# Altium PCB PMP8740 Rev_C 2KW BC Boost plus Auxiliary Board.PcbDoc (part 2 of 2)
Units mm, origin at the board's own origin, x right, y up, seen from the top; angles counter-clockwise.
Board outline 261.75 x 149.86 mm, 2 copper layers (Top Layer, Bottom Layer), stack 1.575 mm thick; 147 components, 79 nets, 365 pads, 168 vias.
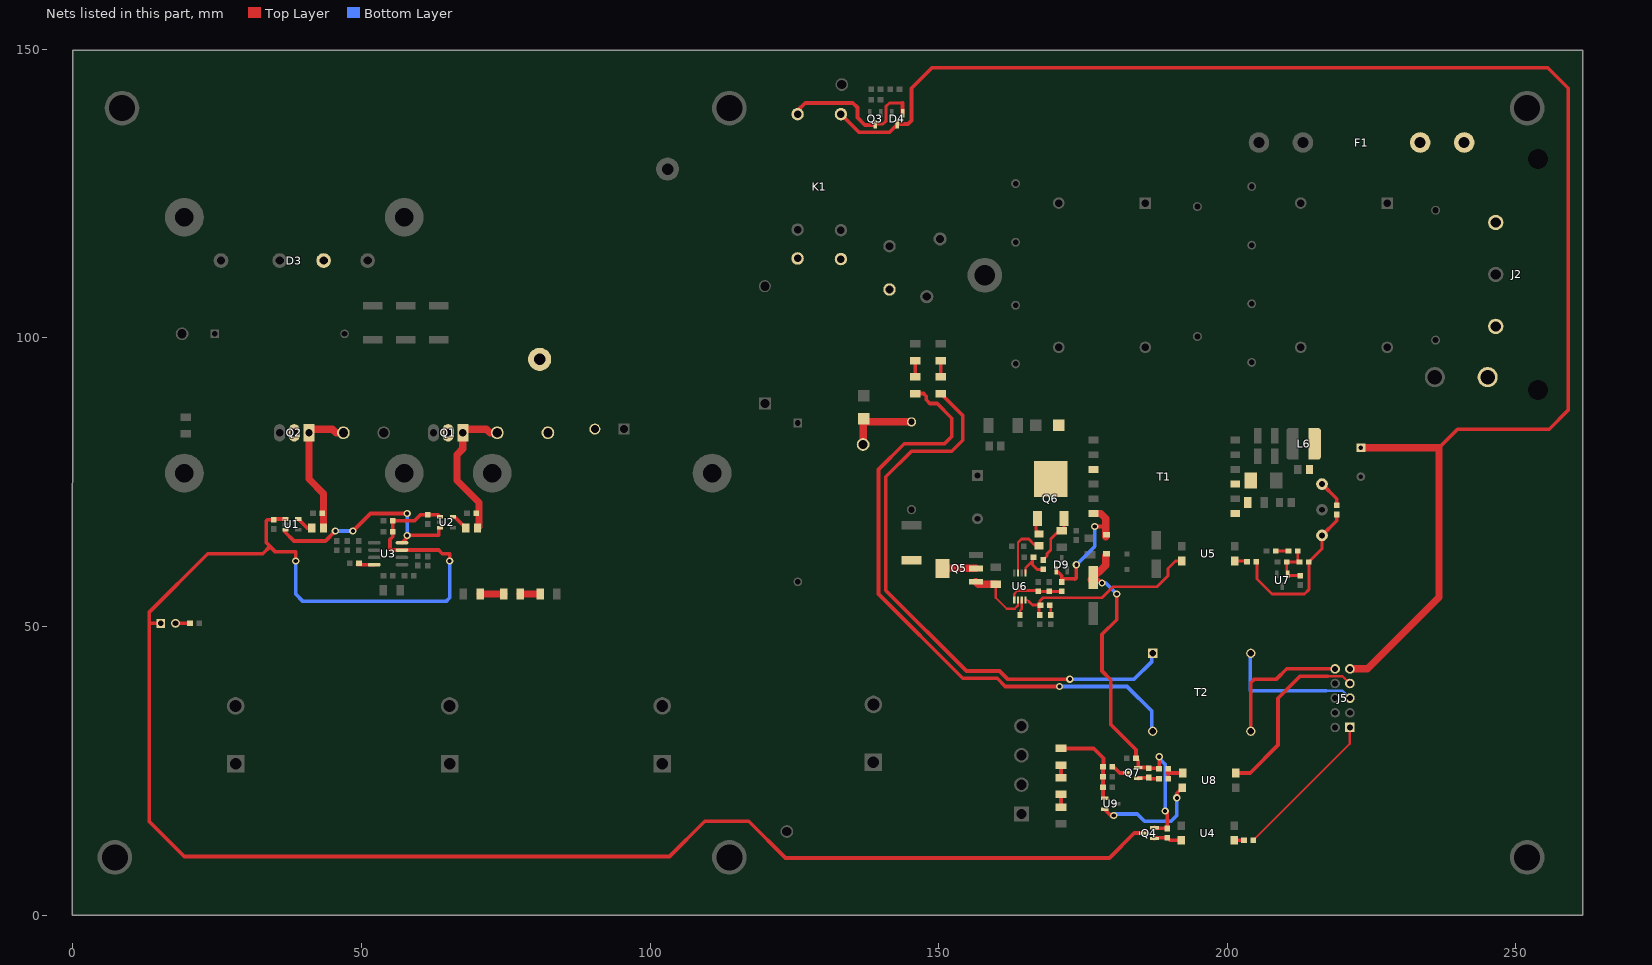
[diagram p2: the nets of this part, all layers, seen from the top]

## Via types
v1: diameter 1.27, hole 0.711, Top Layer to Bottom Layer, tented top, 131 vias
v2: diameter 1.27, hole 0.711, Top Layer to Bottom Layer, 35 vias
v3: diameter 0.889, hole 0.508, Top Layer to Bottom Layer, tented top, 2 vias

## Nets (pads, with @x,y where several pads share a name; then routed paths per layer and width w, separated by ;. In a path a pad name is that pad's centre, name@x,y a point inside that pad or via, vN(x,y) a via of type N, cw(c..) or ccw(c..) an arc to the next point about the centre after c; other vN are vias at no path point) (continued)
NetC34_2: C34.2 R29.1 R32.2 R35.1 U7.1 | length 8.3
  Top Layer w0.508: R29.1@212.214,61.485 R32.2@212.214,63.085 ; R29.1@212.519,61.18 C34.2@210.309,61.18 210.309,59.205 U7.1@210.459,59.055 210.709,58.805 R35.1@212.684,58.805
NetC35_2: C35.2 R32.1 | length 2.2
  Top Layer w0.508: C35.2@208.404,63.085 R32.1@210.614,63.085
NetC36_1: C36.1 R31.1 U6.5 | length 6.1
  Top Layer w0.381: U6.5@165.049,59.268 165.049,60.147 166.243,61.341
  Top Layer w0.508: C36.1@166.408,61.976 166.243,61.811 166.243,61.341 166.243,60.706 167.043,59.906 R31.1@168.148,59.906
NetC37_1: C37.1 U6.3 | length 2.8
  Top Layer w0.381: C37.1@164.089,51.981 164.089,52.731 164.398,53.041 U6.3@164.398,54.605
NetC38_1: C38.1 R33.2 U5.4 U6.4 | length 33.2
  Top Layer w0.305: U6.4@165.049,54.605 165.359,54.605 165.608,54.356
  Top Layer w0.508: 165.608,54.356 166.243,53.721 167.348,53.721 167.348,52.146 C38.1@167.513,51.981 ; R33.2@167.513,53.886 167.513,54.446 168.058,54.991 178.308,54.991 180.213,56.896 187.833,56.896 189.738,58.801 189.738,60.071 191.008,61.341 U5.4@192.11,61.341
NetC39_1: C39.1 R26.1 R27.2 U6.1 | length 9.6
  Top Layer w0.305: 163.068,55.626 163.098,55.596
  Top Layer w0.381: 163.068,55.626 163.703,56.261 ; U6.1@163.098,54.605 163.098,55.596
  Top Layer w0.508: 163.703,56.261 167.099,56.261 C39.1@167.264,56.096 R27.2@169.169,56.096 R26.1@171.323,56.096
NetC40_1: C40.1 R33.1 | length 1.9
  Top Layer w0.508: R33.1@168.948,53.721 169.418,53.251 C40.1@169.418,51.981
NetC42_1: C42.1 R40.1 R42.1 R43.2 U9.1 | length 15.2
  Top Layer w0.635: R40.1@171.196,28.882 176.858,28.882 178.562,27.178 178.562,25.841 R42.1@178.469,25.748 C42.1@178.469,23.97 178.469,20.509 U9.1@178.732,20.246
NetD2_2: D2.2 L1.2 Q1.2 Q2.2 TP2.1
NetD3_3: D3.3 K1.3 K1.4 RT1.2
NetD4_1: D4.1 K1.1 Q3.3 | length 26.8
  Top Layer w0.508: Q3.3@138.983,137.051 140.353,137.051 140.843,137.541 140.843,140.081 141.478,140.716 143.743,140.716
  Top Layer w0.635: K1.1@125.552,138.76 125.552,139.395 126.873,140.716 135.128,140.716 135.928,139.916 135.928,138.176 137.198,136.906 138.838,136.906 Q3.3@138.983,137.051 ; D4.1@143.743,138.951 143.743,140.716
NetD5_1: D5.1 RF1.2 TP15.1 | length 13
  Top Layer w1.27: TP15.1@136.906,81.534 136.906,85.884 D5.1@137.033,86.011 137.593,85.451 RF1.2@145.288,85.451
NetD6_2: D6.2 Q6.4 T1.9
NetD7_2: D7.2 R23.1 T1.1 T1.3
NetD8_2: D8.2 D9.1 R26.2 T1.12 | length 23
  Top Layer w0.635: D9.1@170.373,59.756 171.323,58.806 171.323,58.251 ; R26.2@171.323,57.696 171.323,58.251 ; v1(173.863,60.706) 173.863,58.448 173.601,58.186 173.536,58.251 171.323,58.251 ; v1(177.038,67.332) 178.667,67.332 178.943,67.056
  Top Layer w1.27: T1.12@176.838,69.596 178.068,69.596 178.943,68.721 178.943,67.056 D8.2@178.943,65.518
  Bottom Layer w0.635: v1(173.863,60.706) 177.038,63.881 v1(177.038,67.332)
NetF1_1: F1.1 F1.2 J2.2
NetJ2_1: J2.1 TP11.1
NetJ6_2: J6.2 R48.1 | length 2.5
  Top Layer w0.635: J6.2@17.78,50.546 R48.1@20.282,50.546
NetQ1_1: Q1.1 R2.2 R4.2 TP5.1 | length 28.1
  Top Layer w0.635: R4.2@69.888,69.596 70.104,69.38 R2.2@70.104,67.056
  Top Layer w1.27: R2.2@70.104,67.056 70.358,67.31 70.358,71.501 66.548,75.311 66.548,79.756 67.569,80.777 67.569,84.201 71.628,84.201 72.263,83.566 TP5.1@73.533,83.566
NetQ2_1: Q2.1 R1.2 R3.2 TP4.1 | length 24.4
  Top Layer w1.27: R1.2@43.434,67.056 43.434,73.025 40.899,75.56 40.899,84.201 44.958,84.201 45.593,83.566 TP4.1@46.863,83.566
NetQ4_1: Q4.1 R19.1 U4.4 | length 4.9
  Top Layer w0.635: Q4.1@187.391,13.274 187.541,13.424 R19.1@189.616,13.424 190.086,12.954 U4.4@191.988,12.954
NetQ5_1: Q5.1 R25.1 U6.2 | length 11.8
  Top Layer w0.381: R25.1@159.893,57.351 159.893,54.991 161.798,53.086 163.2,53.086 163.748,53.634 U6.2@163.748,54.605
  Top Layer w1.27: Q5.1@156.443,57.771 156.863,57.351 R25.1@159.893,57.351
NetQ5_2: Q5.2 Q5.4 R18.1 | length 5.8
  Top Layer w1.27: Q5.4@150.643,60.071 Q5.2@156.443,60.071
NetQ6_1: Q6.1 R30.2 | length 2.9
  Top Layer w0.508: Q6.1@167.138,68.736 166.878,68.476 166.878,66.802 R30.2@167.513,66.167
NetQ6_3: Q6.3 R31.2 R34.2 | length 8.9
  Top Layer w0.508: R31.2@168.148,61.58 168.783,62.215 168.783,62.611 169.418,63.246 169.418,65.151 170.868,66.601 R34.2@171.323,66.601 171.698,66.976 Q6.3@171.698,68.736
NetQ7_1: Q7.1 R38.1 R41.2 | length 3.7
  Top Layer w0.635: Q7.1@184.592,23.68 184.742,23.83 R38.1@186.436,23.83 186.652,23.614 R41.2@188.176,23.614
NetQ7_3: Q7.3 R42.2 | length 3.1
  Top Layer w0.635: R42.2@180.069,25.748 180.246,25.748 181.364,24.63 Q7.3@182.692,24.63
NetR1_1: R1.1 U1.5 | length 3
  Top Layer w0.635: U1.5@39.04,68.631 40.615,67.056 R1.1@41.402,67.056
NetR2_1: R2.1 U2.5 | length 3
  Top Layer w0.635: U2.5@65.837,69.012 66.116,69.012 R2.1@68.072,67.056
NetR9_1: R9.1 R10.2 | length 4.1
  Top Layer w1.27: R9.1@70.538,55.626 R10.2@74.623,55.626
NetR10_1: R10.1 R11.1 | length 3.5
  Top Layer w1.27: R10.1@77.523,55.626 R11.1@80.973,55.626
NetR12_2: R12.2 U3.4 | length 2.9
  Top Layer w0.635: R12.2@49.317,60.706 U3.4@52.218,60.706
NetR21_2: R21.2 U4.1 | length 1.7
  Top Layer w0.635: U4.1@201.188,12.954 R21.2@202.908,12.954
NetR24_2: R24.2 R28.2 R29.2 TP9.1 | length 28.5
  Top Layer w0.508: R28.2@205.143,61.341 205.143,58.255 207.772,55.626 213.36,55.626 214.122,56.388 214.122,61.177 R29.2@214.119,61.18 216.408,63.47 TP9.1@216.408,65.786
  Top Layer w0.635: TP9.1@216.408,65.786 218.948,68.326 R24.2@218.948,69.431
NetR28_1: R28.1 U5.1 | length 2.2
  Top Layer w0.508: U5.1@201.31,61.341 R28.1@203.543,61.341
NetR30_1: R30.1 U6.7 | length 9.7
  Top Layer w0.381: U6.7@163.748,59.268 163.748,64.561 164.338,65.151
  Top Layer w0.508: 164.338,65.151 165.608,65.151 166.624,64.135 R30.1@167.513,64.135
NetR36_1: R36.1 R37.2 | length 2.2
  Top Layer w0.635: R36.1@171.196,18.722 R37.2@171.196,20.902
NetR37_1: R37.1 R40.2 | length 2.2
  Top Layer w0.635: R37.1@171.196,23.802 R40.2@171.196,25.982
NetR39_1: R39.1 R41.1 U8.1 | length 5
  Top Layer w0.635: R41.1@189.776,23.614 189.776,24.638 ; U8.1@192.263,24.638 189.776,24.638 ; 189.776,24.638 189.738,24.638 189.738,25.354 189.776,25.316 189.776,24.638
NetR44_1: R44.1 R45.2 | length 2.8
  Top Layer w0.635: R45.2@150.368,93.271 R44.1@150.368,96.086
NetR45_1: R45.1 T2.1 | length 100.5
  Top Layer w0.635: R45.1@150.368,90.371 154.178,86.561 154.178,82.296 152.273,80.391 145.288,80.391 140.843,75.946 140.843,56.261 154.813,42.291 160.528,42.291 161.925,40.894 v2(172.72,40.894)
  Bottom Layer w0.635: v2(172.72,40.894) 183.896,40.894 186.944,43.942 186.944,45.222 T2.1@187.08,45.358
NetR46_1: R46.1 R47.2 | length 2.8
  Top Layer w0.635: R47.2@145.923,93.271 R46.1@145.923,96.086
NetR47_1: R47.1 T2.2 | length 107.6
  Top Layer w0.635: R47.1@145.923,90.371 147.373,90.371 147.828,89.916 147.828,89.281 148.463,88.646 149.733,88.646 152.273,86.106 152.273,82.931 151.003,81.661 144.018,81.661 139.573,77.216 139.573,55.626 154.178,41.021 160.147,41.021 161.544,39.624 v2(170.942,39.624)
  Bottom Layer w0.635: v2(170.942,39.624) 182.626,39.624 186.944,35.306 186.944,31.994 T2.2@187.08,31.858
NetU1_3: U1.3 U2.3 U3.8 | length 36.2
  Top Layer w0.635: U1.3@36.83,66.751 36.703,66.624 36.703,66.421 38.293,64.831 43.749,64.831 v2(45.466,66.548) ; v2(48.514,66.548) 51.562,69.596 v2(57.912,69.596) ; U3.8@57.018,64.516 58.1,65.598 v2(57.912,65.786) ; v2@58.375,65.831 63.373,65.831 63.373,66.878 U2.3@63.627,67.132
  Bottom Layer w0.635: v2(45.466,66.548) v2(48.514,66.548) ; v2(57.912,65.786) v2(57.912,69.596)
NetU8_2: U8.2 U9.2 | length 19.3
  Top Layer w0.635: U9.2@178.732,18.346 179.806,17.272 v2(180.34,17.272) ; v2(191.262,20.32) 191.262,21.122 U8.2@192.238,22.098
  Bottom Layer w0.635: v2(180.34,17.272) 180.594,17.526 184.404,17.526 185.674,16.256 190.246,16.256 191.262,17.272 v2(191.262,20.32)
PFC_ON: J5.1 R21.1 | length 26.5
  Top Layer w0.381: R21.1@204.508,12.954 221.234,29.68 J5.1@221.234,32.512
PG_PFC: J5.7 U8.4 | length 32
  Top Layer w0.381: 217.424,41.402 219.964,41.402 J5.7@221.234,40.132
  Top Layer w0.635: U8.4@201.463,24.638 203.962,24.638 208.788,29.464 208.788,37.592 212.598,41.402 217.424,41.402
VAC: J5.5 T2.4 | length 24.3
  Bottom Layer w0.381: 217.17,38.862 219.964,38.862 J5.5@221.234,37.592
  Bottom Layer w0.635: T2.4@204.08,45.358 203.962,45.24 203.962,38.862 217.17,38.862
VAC_RTN: J5.10 T2.3 | length 24
  Top Layer w0.635: T2.3@204.08,31.858 204.08,40.25 204.724,40.894 208.534,40.894 210.312,42.672 J5.10@218.694,42.672
VCC_FB: C28.1 D4.3 J5.9 K1.6 L6.2 R20.2 R24.1 TP8.1 | length 282.6
  Top Layer w0.635: K1.6@133.071,138.76 136.195,135.636 141.478,135.636 142.793,136.951 D4.3@142.793,137.051 144.688,137.051 145.288,137.651 145.288,143.256 148.844,146.812 255.524,146.812 259.08,143.256 259.08,87.503 255.778,84.201 239.903,84.201 236.677,80.975 ; TP8.1@216.408,74.676 218.948,72.136 R24.1@218.948,71.031 ; 236.728,64.262 236.728,64.516
  Top Layer w1.27: J5.9@221.234,42.672 224.282,42.672 236.677,55.067 236.677,80.975 C28.1@223.144,80.975
VCC_PFC: C4.1 C6.1 C19.1 C20.1 J6.1 Q4.3 U1.1 U2.1 U3.7 | length 325.6
  Top Layer w0.635: J6.1@15.24,50.546 13.208,50.546 ; U1.1@36.83,68.631 34.938,68.631 C4.1@34.798,68.491 33.693,68.491 33.528,68.326 33.528,64.516 34.163,63.881 ; v1(38.608,61.341) 38.608,62.931 35.113,62.931 34.163,63.881 ; U2.1@63.627,69.012 63.259,69.38 C6.1@61.468,69.38 60.236,69.38 59.182,68.326 C20.1@55.418,68.326 C19.1@55.418,66.421 55.418,65.533 54.946,65.061 54.946,63.418 55.118,63.246 U3.7@57.018,63.246 63.373,63.246 64.008,62.611 65.278,62.611 ; v1(65.278,61.341) 65.278,62.622 ; Q4.3@185.491,14.224 183.896,14.224 179.578,9.906 123.444,9.906 117.094,16.256 109.474,16.256 103.378,10.16 19.304,10.16 13.208,16.256 13.208,50.546 ; 13.208,50.546 13.208,52.451 23.368,62.611 32.893,62.611 34.163,63.881
  Bottom Layer w0.635: v1(38.608,61.341) 38.608,55.626 39.878,54.356 64.643,54.356 65.278,54.991 v1(65.278,61.341)
VCC_PRIMARY: C26.1 C41.1 D8.1 Q4.2 Q7.2 R19.2 R38.2 R39.2 | length 65.3
  Top Layer w0.635: C26.1@176.403,58.091 177.748,58.091 v1(178.308,57.531) ; v1(180.848,55.626) 180.848,51.181 178.308,48.641 178.308,42.291 179.832,40.767 179.832,33.02 184.188,28.664 C41.1@184.188,27.178 184.592,26.774 Q7.2@184.592,25.58 186.286,25.58 R38.2@186.436,25.43 188.138,25.43 R39.2@188.176,25.392 ; Q4.2@187.391,15.174 187.541,15.024 R19.2@189.616,15.024 189.616,17.648 v1(189.23,18.034) ; R39.2@188.214,25.43 v2(188.214,27.432)
  Top Layer w1.27: C26.1@176.403,58.091 178.943,60.631 D8.1@178.943,62.244
  Bottom Layer w0.635: v1(178.308,57.531) 178.943,57.531 v1(180.848,55.626) ; v2(188.214,27.432) 188.214,27.178 189.23,26.162 v1(189.23,18.034)
pads on no net: D4.2 D9.2 HS1.1 HS2.1 HS2.2 HS3.2 J2.MH1 J2.MH2 T1.2 T1.5 T1.8 T1.10

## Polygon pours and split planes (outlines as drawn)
GND-P on Bottom Layer "Bottom Layer-No Net 8" (solid, pour order 50): 30.353,96.901 31.623,98.171 31.623,98.806 102.108,98.806 135.763,65.151 149.733,65.151 151.003,66.421 151.003,70.231 152.908,72.136 152.908,72.771 163.703,72.771 165.608,70.866 191.008,70.866 192.913,68.961 192.913,60.706 192.865,58.435 192.786,43.434 192.786,12.446 124.714,12.446 117.856,19.05 109.982,19.05 103.632,12.7 18.542,12.7 10.16,21.082 10.033,51.181 11.938,53.086 72.263,53.086 72.263,68.961 79.248,75.946 79.248,80.391 77.343,82.296 77.343,86.741 76.708,87.376 76.581,87.249 64.008,87.249 63.373,86.614 63.373,84.836 60.833,84.836 60.833,86.741 60.323,87.251 60.198,87.251 60.073,87.376 37.338,87.376 36.703,86.741 36.703,84.201 34.798,84.201 34.798,85.471 30.353,89.916
NetF1_1 on Bottom Layer "Top Layer-No Net" (solid, pour order 53): 250.772,118.584 241.231,118.584 239.936,119.92 239.936,123.216 237.302,125.933 237.302,126.111 234.496,126.111 229.108,130.937 229.108,136.779 230.378,138.176 244.037,138.269 245.159,137.111 245.159,134.796 245.11,133.096 245.11,129.032 251.333,123.558 251.333,119.163
GND-S on Bottom Layer "Bottom Layer-No Net 9" (solid, pour order 81): 233.68,86.36 237.49,82.55 237.49,11.684 201.168,11.684 201.168,86.36
AC1 on Bottom Layer "Bottom Layer-No Net 6" (solid, pour order 69): 154.813,102.052 156.083,103.251 161.163,103.251 160.528,103.251 163.703,100.252 167.513,100.252 168.148,100.252 170.688,102.651 175.133,102.651 176.403,101.452 176.403,94.255 174.498,92.456 156.083,92.456 154.813,93.655 154.813,102.052
AC2 on Bottom Layer "M1 Board Outline-No Net 1" (solid, pour order 66): 154.178,136.906 155.448,138.176 156.083,138.176 173.863,138.176 175.133,136.906 175.133,120.396 174.498,119.761 170.688,119.761 167.513,122.936 163.068,122.936 160.528,120.396 156.083,120.396 154.178,122.301
NetC11_1 on Bottom Layer "Bottom Layer-No Net" (solid, pour order 55): 204.978,138.176 224.028,138.176 225.298,137.018 225.298,130.07 232.918,123.123 236.728,123.123 237.998,121.965 237.998,118.491 219.583,118.491 218.313,119.649 218.313,125.439 213.868,129.491 206.248,129.491 203.708,131.228 203.708,137.018
EARTH on Bottom Layer "Top Layer-No Net 1" (solid, pour order 57): 154.813,116.586 156.027,117.856 161.49,117.856 164.526,121.031 166.954,121.031 170.596,117.221 200.341,117.221 200.948,117.856 208.84,117.856 210.742,115.866 210.876,115.866 210.957,115.951 250.119,115.951 251.333,114.681 251.333,107.061 250.119,105.791 210.661,105.791 208.84,103.886 201.555,103.886 199.734,105.791 170.596,105.791 166.954,101.981 164.526,101.981 161.49,105.156 156.027,105.156 154.813,107.061
NetC2_2 on Bottom Layer "Bottom Layer-No Net 2" (solid, pour order 61): 206.248,127.353 213.868,127.353 213.233,127.353 215.138,125.644 215.138,119.948 213.868,118.808 211.328,118.808 209.423,120.517 199.898,120.517 199.263,119.948 199.068,119.948 180.213,119.948 179.578,120.517 179.578,137.037 180.848,138.176 181.483,138.176 198.628,138.176 199.898,137.037 199.898,130.201 199.898,129.632 202.438,127.353
NetC12_2 on Bottom Layer "Top Layer-No Net 2" (solid, pour order 63): 180.848,103.251 198.628,103.251 200.533,101.346 209.423,101.346 211.328,103.251 216.408,103.251 217.043,102.616 217.043,93.091 214.503,90.551 195.453,90.551 193.548,92.456 182.118,92.456 180.848,93.726 180.848,101.981 182.118,103.251
GND-P on Bottom Layer "Bottom Layer-No Net 7" (solid, pour order 48): 25.908,80.645 29.972,80.645 34.798,85.471 36.703,85.471 36.703,81.534 37.338,80.899 56.261,80.899 60.833,85.471 63.373,85.471 63.373,81.915 64.643,80.645 65.659,80.645 68.453,77.851 68.453,71.501 70.993,68.961 70.993,54.451 25.368,54.451 25.273,54.356 25.273,80.01 25.908,80.645
AC1 on Bottom Layer "Bottom Layer-No Net 5" (solid, pour order 64): 109.093,115.316 116.713,107.696 116.713,100.711 53.848,100.711 50.673,103.886 44.323,103.886 41.148,100.711 32.893,100.711 31.623,101.981 31.623,114.681 32.258,115.316 37.338,115.316 41.783,110.871 53.848,110.871 57.023,115.316
AC2 on Bottom Layer "Bottom Layer-No Net 10" (solid, pour order 46): 123.063,130.556 140.843,130.556 148.463,138.176 149.098,138.176 157.353,138.176 156.718,137.541 156.718,120.396 153.543,120.396 155.448,120.396 148.463,113.411 140.208,113.411 140.208,115.316 137.033,118.491 137.668,117.856 124.333,117.856 123.063,119.126 123.063,124.206 123.063,129.921
AC1 on Bottom Layer "Bottom Layer-No Net 4" (solid, pour order 42): 107.823,109.601 114.808,109.601 123.063,101.346 142.748,101.346 147.193,105.791 147.193,107.696 150.368,107.696 154.813,103.251 159.893,103.251 159.893,92.456 153.543,83.566 121.793,83.566 104.648,100.711 104.013,100.711
NetD3_3 on Bottom Layer "Bottom Layer-No Net 3" (solid, pour order 45): 39.243,141.986 102.108,141.986 109.093,132.461 121.158,132.461 121.158,118.491 123.063,116.586 135.763,116.586 138.938,110.871 144.018,110.871 144.018,106.426 140.843,103.251 124.333,103.251 110.363,116.586 55.753,116.586 51.308,112.141 43.053,112.141 39.243,115.951
NetC11_2 on Bottom Layer "Bottom Layer-No Net 1" (solid, pour order 59): 238.76,103.124 238.76,91.44 225.044,91.44 223.603,93.088 222.423,94.358 222.423,102.613 223.013,103.248
NetJ2_1 on Bottom Layer "Bottom Layer-No Net 11" (solid, pour order 44): 240.792,102.997 240.919,103.124 250.19,103.124 251.206,102.108 250.952,101.854 250.952,94.234 248.158,91.44 240.792,91.44
+390V on Top Layer "Top Layer-No Net 5" (solid, pour order 51): 94.488,92.456 97.028,94.996 124.968,94.996 131.953,88.011 131.953,75.946 129.413,73.406 129.413,54.991 156.083,30.226 161.798,24.511 166.243,24.511 168.783,21.971 168.783,14.986 166.878,12.7 122.682,12.7 116.84,18.796 109.728,18.796 103.378,12.446 22.098,12.446 20.193,14.351 20.193,31.496 76.708,31.496 84.963,39.751 84.963,71.12 94.488,80.645
NetF1_1 on Top Layer "Top Layer-No Net" (solid, pour order 52): 250.769,118.61 241.173,118.61 239.871,119.938 239.871,123.214 237.222,125.914 237.222,126.091 234.4,126.091 229.108,131.064 229.108,136.779 230.378,138.176 243.995,138.176 245.124,137.025 245.124,134.723 245.11,134.62 245.11,129.54 251.333,123.558 251.333,119.185
NetC2_2 on Top Layer "Bottom Layer-No Net 2" (solid, pour order 60): 213.233,127.353 215.138,125.644 215.138,119.948 213.868,118.808 211.328,118.808 209.423,120.517 199.898,120.517 199.263,119.948 180.213,119.948 179.578,120.517 179.578,137.037 180.848,138.176 198.628,138.176 199.898,137.037 199.974,129.209 201.422,127.254
GND-S on Top Layer "Bottom Layer-No Net 9" (solid, pour order 80): 233.802,86.348 237.612,82.538 237.744,12.192 201.422,12.192 201.29,40.374 201.29,86.348
GND-P on Top Layer "Top Layer-No Net 10" (solid, pour order 76): 153.543,69.596 156.083,72.136 160.528,72.136 162.433,70.231 173.228,70.231 175.768,72.771 185.293,72.771 192.913,65.151 192.786,12.63 176.53,12.7 176.53,43.688 163.83,43.688 160.274,47.498 157.988,49.911 155.448,52.451 155.448,65.151 153.543,67.056
GND-P on Top Layer "Top Layer-No Net 6" (solid, pour order 70): 50.583,101.981 69.088,101.981 70.358,100.711 70.358,96.266 50.673,96.266 50.038,96.901 50.038,101.346 50.583,101.891
NetC7_2 on Top Layer "Top Layer-No Net 7" (solid, pour order 71): 49.403,116.586 65.913,116.586 65.913,103.251 49.069,103.251 49.069,97.086 48.953,97.086 48.133,96.266 35.433,96.266 32.258,99.441 32.258,107.696 34.798,110.236 46.228,110.236 48.133,112.141 48.133,115.316
NetC7_1 on Top Layer "M1 Board Outline-No Net" (solid, pour order 65): 25.908,136.906 104.648,136.906 121.158,123.571 121.158,107.696 119.253,105.791 101.473,105.791 96.393,100.711 75.438,100.711 68.453,107.696 68.453,117.856 60.198,126.111 54.483,126.111 52.578,124.206 52.578,122.936 46.863,117.221 32.893,117.221 29.718,114.046 29.718,99.441 27.178,96.901 15.113,96.901 13.843,98.171 13.843,112.776 15.113,114.046 22.098,114.046 24.638,116.586 24.638,135.636
EARTH on Top Layer "Top Layer-No Net 1" (solid, pour order 56): 154.764,116.586 155.979,117.856 161.445,117.856 164.482,121.031 166.911,121.031 170.555,117.221 200.315,117.221 200.923,117.856 208.818,117.856 210.722,115.866 210.856,115.866 210.937,115.951 250.118,115.951 251.333,114.681 251.333,107.061 250.118,105.791 210.64,105.791 208.818,103.886 201.53,103.886 199.708,105.791 170.555,105.791 166.911,101.981 164.482,101.981 161.445,105.156 155.979,105.156 154.764,107.061
NetC11_1 on Top Layer "Bottom Layer-No Net" (solid, pour order 54): 204.978,138.176 224.028,138.176 225.298,137.018 225.298,130.07 232.918,123.123 236.728,123.123 237.998,121.965 237.998,118.491 219.583,118.491 218.313,119.649 218.313,125.439 213.868,129.491 206.248,129.491 203.708,131.228 203.708,137.018
NetC12_2 on Top Layer "Top Layer-No Net 2" (solid, pour order 62): 180.848,103.251 198.628,103.251 200.533,101.346 209.423,101.346 211.328,103.251 216.408,103.251 217.043,102.616 217.043,93.091 214.503,90.551 195.453,90.551 193.548,92.456 182.118,92.456 180.848,93.726 180.848,101.981 182.118,103.251
GND-P on Top Layer "Bottom Layer-No Net 7" (solid, pour order 47): 25.908,80.645 29.972,80.645 34.798,85.471 36.703,85.471 36.703,81.534 37.338,80.899 56.261,80.899 60.833,85.471 63.373,85.471 63.373,81.915 64.643,80.645 65.659,80.645 68.453,77.851 68.453,71.501 70.993,68.961 70.993,54.451 25.368,54.451 25.273,54.356 25.273,80.01 25.908,80.645
no net on Top Layer "Bottom Layer-No Net 6" (solid, pour order 68): 154.813,101.981 156.083,103.251 160.528,103.251 163.703,100.076 168.148,100.076 170.688,102.616 175.133,102.616 176.403,101.346 176.403,93.726 175.133,92.456 157.353,92.456 154.813,94.996
NetC24_1 on Top Layer "M5 Assembly Top-No Net" (solid, pour order 72): 157.988,89.281 158.623,89.916 161.798,89.916 174.498,89.916 176.403,88.011 178.308,88.011 178.703,87.616 178.703,81.661 175.768,81.661 175.768,85.471 173.863,87.376 161.163,87.376 160.528,86.741 160.528,84.201 159.893,84.201 159.258,83.566 159.258,74.676 158.623,74.041 154.813,74.041 147.828,67.056 143.383,67.056 143.383,74.676 146.558,77.851 156.083,77.851 157.353,79.121 157.353,88.646 157.988,89.281
NetC25_2 on Top Layer "Top Layer-No Net 8" (solid, pour order 74): 163.068,86.106 167.513,86.106 167.513,83.086 167.358,82.931 163.703,82.931 163.068,82.931 161.773,81.636 161.773,80.645 161.519,80.391 160.528,80.391 160.528,82.386 160.528,82.931 161.163,83.566 161.798,83.566 163.068,84.836 163.068,86.106
NetQ5_2 on Top Layer "Top Layer-No Net 9" (solid, pour order 75): 143.613,64.516 152.908,64.516 152.908,56.896 151.003,54.991 145.288,54.991 143.383,56.896 143.383,57.531 143.383,64.516
NetD6_2 on Top Layer "Top Layer-No Net 3" (solid, pour order 73): 168.148,81.661 169.418,82.931 169.418,85.471 173.863,85.471 174.498,84.836 174.498,78.486 175.133,77.851 177.673,77.851 177.673,76.581 175.133,76.581 174.498,75.946 174.498,74.041 172.718,72.136 162.433,72.136 161.163,73.406 161.163,78.486 163.068,80.391 163.068,81.026 163.703,81.661
NetC27_2 on Top Layer "Top Layer-No Net 11" (solid, pour order 77): 207.518,85.344 213.106,85.344 213.106,70.866 212.598,70.358 210.566,70.358 210.566,70.522 210.312,70.776 210.312,72.547 209.798,73.061 207.355,73.061 206.502,73.914 206.502,84.582 207.264,85.344 207.518,85.344
NetD7_2 on Top Layer "Top Layer-No Net 12" (solid, pour order 78): 200.152,76.962 205.994,76.962 205.994,73.317 205.651,73.317 204.978,72.644 204.978,71.628 204.47,71.12 204.47,69.342 203.454,68.326 200.152,68.326 200.152,76.962
VCC_FB on Top Layer "Top Layer-No Net 13" (solid, pour order 79): 214.122,85.344 224.536,85.344 225.298,84.582 225.298,79.236 224.015,77.953 220.701,77.953 220.472,77.724 220.472,74.93 218.44,72.898 213.614,72.898 213.614,84.836 214.122,85.344
no net on Top Layer "M1 Board Outline-No Net 1" (solid, pour order 67): 154.178,131.191 164.973,138.176 173.863,138.176 175.133,136.906 175.133,120.396 174.498,119.761 170.688,119.761 167.513,122.936 163.068,122.936 160.528,120.396 156.083,120.396 154.178,122.301
NetD2_2 on Top Layer "Top Layer-No Net 4" (solid, pour order 49): 37.338,91.186 41.148,94.996 72.39,94.996 73.914,98.806 92.456,98.806 92.583,82.931 90.043,80.391 78.613,80.391 77.343,81.661 77.343,86.741 76.708,87.376 66.65,87.376 66.548,87.274 66.446,87.274 65.913,86.741 65.913,83.566 64.008,83.566 64.008,86.741 63.373,87.376 39.878,87.376 39.243,86.741 39.243,83.566 37.338,83.566
NetC11_2 on Top Layer "Bottom Layer-No Net 1" (solid, pour order 58): 239.014,102.87 239.014,91.44 224.536,91.44 223.315,92.847 222.719,93.482 222.123,94.117 222.123,102.372 222.719,103.007
NetJ2_1 on Top Layer "Bottom Layer-No Net 11" (solid, pour order 43): 240.792,102.939 240.919,103.066 250.19,103.066 251.206,102.05 250.952,101.796 250.952,94.176 248.158,91.44 240.792,91.44

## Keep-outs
Keep-Out Layer:
  lines w0.254: -0.127,87.63 -0.127,0 ; 0,149.86 261.62,149.86 261.62,0 ; 125.73,-0.127 0,-0.127 ; -0.127,0 ccw(c0,0) 0,-0.127 ; -0.127,0 ccw(c0,0) 0,-0.127 ; -0.127,0 ccw(c0,0) 0,-0.127 ; -0.127,0 ccw(c0,0) 0,-0.127 ; -0.127,0 ccw(c0,0) 0,-0.127 ; -0.127,0 ccw(c0,0) 0,-0.127
  text ".Layer_Name" at 14.656,-21.806 h1.52

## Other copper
Top Layer:
  rectangle net EARTH: 154.813,107.061 163.068,114.681
  rectangle net EARTH: 239.903,108.331 250.698,113.411
  rectangle net NetJ2_1: 240.792,97.282 251.147,102.997
  rectangle net NetF1_1: 240.284,119.126 251.079,124.206
  text ".Layer_Name" at 14.656,-21.806 h1.52
Bottom Layer:
  rectangle net GND-P: 34.163,84.201 36.703,86.106
  rectangle net GND-P: 60.833,84.836 63.373,86.741
  rectangle net NetF1_1: 240.538,118.999 250.698,123.698
  rectangle net EARTH: 154.813,107.061 161.798,114.681
  rectangle net EARTH: 239.268,107.696 251.333,113.411
  rectangle net NetJ2_1: 240.792,97.282 251.147,102.997
  pour cut-out: 156.972,45.466 169.926,32.512 169.926,11.938 170.434,11.938 170.434,33.02 157.988,45.466
  text ".VersionControl_RevNumber" at 99.339,5.575 h1.52
  text "SVN:" at 106.426,5.575 h1.52
  text "UL94V-0" at 64.249,2.197 h1.52
  text ".Layer_Name" at 14.656,-21.806 h1.52

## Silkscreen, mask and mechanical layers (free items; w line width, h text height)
Top Overlay:
  circle w0.152: c223.231,78.549 r5.425
  circle w0.254: c28.194,31.242 r17.993
  circle w0.254: c65.278,31.242 r17.993
  circle w0.254: c101.854,31.242 r17.993
  circle w0.254: c138.938,31.496 r17.993
  text "This document can handle board shapes up to 7.9in x 10in, although" at 154.178,290.195 h1.52
  text "our panel vendors top out at 7in x 10in." at 154.178,287.044 h1.52
  text "To re-size the board shape, do the following:" at 155.575,283.893 h1.52
  text "Select lines on M1 Board Outline and delete (easy in single layer mode...shift+s)" at 157.099,280.742 h1.52
  text "Draw a rectangle using lines (example will be for a 4\" x 6\" board" at 157.099,277.591 h1.52
  text "Enter Place Line mode (keyboard pl)" at 162.433,274.44 h1.52
  text "keyboard jo to jump to origin, hit enter" at 162.433,271.288 h1.52
  text "keyboard jl to jump to location, set x to 6000, hit enter twice" at 162.433,268.137 h1.52
  text "keyboard jl to jump to location, set x to 6000 and y to 4000, hit enter twice" at 166.878,265.684 h1.52
  text "keyboard jl to jump to location, set x to 0 and y to 4000, hit enter twice" at 162.433,261.835 h1.52
  text "keyboard jo to jump to origin, hit enter" at 162.433,258.684 h1.52
  text "Hit ESC twice to exit place line mode" at 162.433,255.533 h1.52
  text "Select lines on M1 Board Outline" at 157.099,251.874 h1.52
  text "Menu Design|Board Shape|Define from Selected Objects (keyboard dsd)" at 157.099,249.231 h1.52
  text "To define a Keep-Out that mirrors the board outline:" at 154.178,246.08 h1.52
  text "Menu Design|Board Shape|Create Primitives From Board Shape (keyboard dsp)" at 157.099,242.929 h1.52
  text "Set the Keep-Out Layer as the layer, set width as preferred" at 162.433,239.777 h1.52
  text "Ensure Route Tool Outline is selected, hit enter" at 162.433,236.626 h1.52
  text "If you re-size the board, don't forget to move the drill table strings on the" at 154.178,228.422 h1.52
  text "Drill Drawing Layer...they should be just to the right of your board shape" at 159.08,225.73 h1.52
  text "TEXAS INSTRUMENTS" at 215.646,19.812 h1.52
  text "PFC Boost Stage + Aux." at 215.646,16.764 h1.52
  text "PMP8740 Rev.C" at 215.646,13.97 h1.52
  text "Oct. 2014" at 215.646,10.922 h1.02
  text ".Layer_Name" at 14.656,-21.806 h1.52
Bottom Overlay:
  rectangle: 16.713,4.826 24.333,7.366
  text ".PCB_Rev" at 28.651,5.08 h1.52
  text ".PRJ_Number" at 41.25,5.08 h1.52
  text "-" at 25.984,4.813 h1.52
  text ".Layer_Name" at 14.656,-21.806 h1.52
Top Paste:
  text ".Layer_Name" at 14.656,-21.806 h1.52
Bottom Paste:
  text ".Layer_Name" at 14.656,-21.806 h1.52
Top Solder:
  text ".Layer_Name" at 14.656,-21.806 h1.52
  text ".Layer_Name" at 14.656,-21.806 h1.52
Bottom Solder:
  text ".Layer_Name" at 14.656,-21.806 h1.52
Drill Guide:
  text ".Layer_Name" at 14.656,-21.806 h1.52
M1 Board Outline:
  lines w0.254: 0,0 0,149.86 261.62,149.86 261.62,0 0,0
  text ".Layer_Name" at 14.656,-21.806 h1.52
M2 Board Dimensions:
  rectangle: -0.013,-7.252 3.162,-4.077
  rectangle: 3.162,-10.427 12.687,-7.252
  lines w0.178: -0.013,-7.252 25.387,-7.252 ; 3.162,-10.427 3.162,-4.077 ; 6.337,-10.427 6.337,-4.077 ; 12.687,-10.427 12.687,-4.077 ; 19.037,-10.427 19.037,-4.077 ; -0.013,-10.427 25.387,-10.427 25.387,-4.077 -0.013,-4.077 -0.013,-10.427
  lines w0.254: -0.013,-12.078 -0.013,-11.57 ; 1.511,-12.332 -0.013,-11.824 ; 1.511,-11.316 -0.013,-11.824 ; 6.187,-11.824 -0.013,-11.824 ; 19.188,-11.824 25.387,-11.824 ; 23.863,-12.332 25.387,-11.824 ; 23.863,-11.316 25.387,-11.824 ; 25.387,-12.078 25.387,-11.57
  text "25.4 (mm)" at 6.441,-12.738 h1.52
  text ".Layer_Name" at 14.656,-21.806 h1.52
M3 3D STEP Top:
  text ".Layer_Name" at 14.656,-21.806 h1.52
M4 3D STEP Bottom:
  text ".Layer_Name" at 14.656,-21.806 h1.52
M5 Assembly Top:
  lines w0.254: -7.417,-23.626 160.223,-23.626 ; -7.417,-18.462 160.274,-18.462 ; -7.417,-13.297 -7.417,-28.791 94.31,-28.791 160.274,-28.791 160.274,-13.297 -7.404,-13.297 -7.404,-28.791 32.614,-28.791 ; 11.938,57.277 11.938,55.372 118.618,55.372 118.618,57.277 ; 11.938,80.645 118.618,80.645 ; 11.938,116.967 65.278,116.967 ; 11.938,140.335 11.938,141.986 65.278,141.986 65.278,140.335 ; 55.194,-28.791 55.194,-13.297 ; 87.376,-18.462 87.376,-13.297 ; 108.712,-18.462 108.712,-13.297 ; 124.511,-28.956 124.511,-23.804
  lines w0.5: 67.183,92.964 67.183,133.096 116.183,133.096 116.183,92.964 67.183,92.964
  text "COMPONENTS MARKED 'DNP' SHOULD NOT BE POPULATED." at 29.299,-8.09 h1.52
  text "ASSEMBLY VARIANT:" at 29.286,-11.024 h1.52
  text ".VariantName" at 55.601,-11.024 h1.52
  text "PCB VIEWED FROM TOP SIDE" at -5.804,-16.654 h1.52
  text "BOARD #:" at 57.099,-16.654 h1.52
  text ".PRJ_Number" at 70.955,-16.654 h1.52
  text "REV:" at 92.405,-16.654 h1.52
  text ".PCB_Rev" at 99.809,-16.654 h1.52
  text "SVN REV:" at 113.69,-16.654 h1.52
  text ".VersionControl_RevNumber" at 126.543,-16.654 h1.52
  text "IGNORE ->" at -5.804,-21.806 h1.52
  text "PLOT NAME =" at -5.804,-27.034 h1.52
  text ".plot_File_Name" at 14.656,-27.034 h1.52
  text "GENERATED    :" at 57.15,-27.034 h1.52
  text ".Print_Date" at 79.235,-27.034 h1.52
  text ".Print_Time" at 97.752,-27.034 h1.52
  text "TEXAS INSTRUMENTS" at 129.87,-27.034 h1.52
M6 Assembly Bottom:
  lines w0.254: -7.429,-18.474 160.261,-18.474 ; -7.379,-23.639 160.261,-23.639 ; 28.334,-28.969 28.334,-23.817 ; 44.133,-18.474 44.133,-13.31 ; 65.468,-18.474 65.468,-13.31 ; 97.65,-28.804 97.65,-13.31 ; 120.231,-28.804 160.249,-28.804 160.249,-13.31 -7.429,-13.31 -7.429,-28.804 58.534,-28.804 160.261,-28.804 160.261,-13.31
  text "COMPONENTS MARKED 'DNP' SHOULD NOT BE POPULATED." at 154.991,-8.077 h1.52
  text ".VariantName" at 128.473,-11.024 h1.52
  text "ASSEMBLY VARIANT:" at 154.864,-11.024 h1.52
  text ".VersionControl_RevNumber" at 26.302,-16.667 h1.52
  text "SVN REV:" at 39.154,-16.667 h1.52
  text ".PCB_Rev" at 53.035,-16.667 h1.52
  text "REV:" at 60.439,-16.667 h1.52
  text ".PRJ_Number" at 81.89,-16.667 h1.52
  text "BOARD #:" at 95.745,-16.667 h1.52
  text "PCB VIEWED FROM BOTTOM SIDE" at 158.648,-16.667 h1.52
  text "IGNORE ->" at 64.715,-21.806 h1.52
  text "TEXAS INSTRUMENTS" at 22.974,-27.047 h1.52
  text ".Print_Time" at 55.093,-27.047 h1.52
  text ".Print_Date" at 73.609,-27.047 h1.52
  text "GENERATED    :" at 95.694,-27.047 h1.52
  text ".plot_File_Name" at 138.189,-27.047 h1.52
  text "PLOT NAME =" at 158.648,-27.047 h1.52
M9 Title Sheet:
  drawing of 57 lines, arcs and shapes, not listed
  text "1" at 18.792,204.127 h1.78
  text "2" at 82.182,204.127 h1.78
  text "3" at 145.411,204.127 h1.78
  text "4" at 209.08,204.127 h1.78
  text "5" at 272.555,204.127 h1.78
  text "6" at 336.182,204.127 h1.78
  text "A" at -10.579,175.095 h1.78
  text "A" at 365.341,175.095 h1.78
  text "B" at -10.579,114.643 h1.78
  text "B" at 365.091,114.643 h1.78
  text "C" at -10.579,54.318 h1.78
  text "C" at 365.091,54.318 h1.78
  text "PROJECT TITLE:" at 287.875,7.048 h1.14
  text ".PRJ_Title" at 289.145,3.662 h1.78
  text "DESIGNED FOR:" at 288.125,-0.597 h1.14
  text ".PRJ_Customer" at 289.395,-4.153 h1.78
  text "D" at -10.579,-5.88 h1.78
  text "D" at 365.341,-5.88 h1.78
  text "FILE NAME:" at 288.125,-8.217 h1.14
  text ".PCB_File_Name_No_Path" at 289.395,-11.265 h1.78
  text "Texas Instruments (TI) and/or its licensors do not warrant the accuracy or completeness of this specification" at 161.9,-15.376 h1.14
  text "ENGINEER:" at 288.125,-15.583 h1.14
  text "LAYOUT BY:" at 326.352,-15.583 h1.14
  text "or any information contained therein. TI and/or its licensors do not warrant that this design will meet" at 160.757,-18.237 h1.14
  text ".PRJ_Engineer" at 289.395,-19.52 h1.78
  text ".PCB_Layout" at 327.635,-19.52 h1.78
  text "the specifications, will be suitable for your application or fit for any particular purpose, or will operate in" at 160.757,-21.099 h1.14
  text ".Layer_Name" at 14.656,-21.806 h1.52
  text "ALTIUM DESIGNER VERSION:" at 326.352,-23.457 h1.14
  text "an implementation. TI and/or its licensors do not warrant that the design is production worthy. You should" at 160.757,-23.961 h1.14
  text "completely validate and test your design implementation to confirm the system functionality for your application." at 161.9,-26.822 h1.14
  text ".print_Scale" at 289.395,-26.843 h1.78
  text ".Application_BuildNumber" at 327.635,-26.843 h1.78
  text "1" at 18.792,-32.093 h1.78
  text "2" at 82.182,-32.093 h1.78
  text "3" at 145.411,-32.093 h1.78
  text "4" at 209.08,-32.093 h1.78
  text "5" at 272.555,-32.093 h1.78
  text "6" at 336.182,-32.093 h1.78
M10 Fab Notes:
  drawing of 212 lines, arcs and shapes, not listed
  text "DESIGN INFORMATION" at 314.478,172.974 h1.52
  text "(REFER ALSO ARRAY/PANEL PROFILING INFORMATION)" at 305.294,168.866 h1.52
  text "BOARD SIZE" at 287.87,168.758 h1.52
  text "3450MIL" at 299.613,165.511 h1.52
  text "X" at 312.457,165.511 h1.52
  text "4950MIL" at 318.333,165.511 h1.52
  text "Number of Layers :" at 298.106,160.503 h1.52
  text "2" at 325.914,160.249 h1.52
  text "MIN. TRACK WIDTH:" at 298.106,156.972 h1.52
  text "8" at 325.951,156.972 h1.52
  text "MIL" at 329.881,156.972 h1.52
  text "MIN. CLEARANCE:" at 298.106,153.619 h1.52
  text "8" at 325.951,153.619 h1.52
  text "MIL" at 329.881,153.619 h1.52
  text "MIN. VIA PAD SIZE:" at 298.106,150.266 h1.52
  text "24" at 325.189,150.266 h1.52
  text "MIL" at 329.881,150.266 h1.52
  text "0.05mm (2MIL)" at 315.759,146.667 h1.52
  text "MINIMUM ANNULAR RING" at 289.744,146.558 h1.52
  text "EXTERNAL" at 333.742,146.558 h1.52
  text "PER" at 294.824,143.561 h1.52
  text "IPC-D-275 CLASS 2 LEVEL C" at 300.412,143.561 h1.52
  text "MIL, HOLES" at 338.213,140.709 h1.52
  text "+/-" at 328.244,140.691 h1.52
  text "+/-" at 349.936,140.691 h1.52
  text "REGISTRATION TOLERANCES:" at 289.744,140.564 h1.52
  text "METAL" at 320.218,140.564 h1.52
  text "5" at 334.853,140.564 h1.52
  text "3" at 356.012,140.564 h1.52
  text "MIL" at 358.964,140.564 h1.52
  text "MATERIAL:" at 287.844,135.243 h1.52
  text "FR-4 High Tg" at 312.651,131.679 h1.52
  text "FR-408" at 298.288,131.461 h1.52
  text "X" at 308.753,131.461 h1.52
  text "OTHER" at 336.084,131.461 h1.52
  text "62 MIL (1.6mm) +/-10%" at 306.419,127.328 h1.52
  text "THICKNESS:" at 289.494,127.219 h1.52
  text "X" at 303.164,127.219 h1.52
  text "OTHER" at 339.055,127.219 h1.52
  text "TOLERANCE:" at 289.494,123.206 h1.52
  text "X" at 310.812,123.206 h1.52
  text "ANSI IPC-6012 TYPE 3 CLASS 2" at 315.561,123.206 h1.52
  text "OTHER +/-" at 315.56,119.244 h1.52
  text "BOW & TWIST:" at 289.494,115.256 h1.52
  text "X" at 310.812,115.256 h1.52
  text "ANSI IPC-6012 TYPE 3 CLASS 2" at 315.561,115.256 h1.52
  text "OTHER +/-" at 315.56,111.23 h1.52
  text "COPPER THICKNESS (FINISHED):" at 287.595,107.788 h1.52
  text "1.4MIL (1oz)" at 309.947,103.909 h1.52
  text "2MIL (1.4oz)" at 329.429,103.909 h1.52
  text "2.8MIL (2oz)" at 347.895,103.909 h1.52
  text "X" at 344.932,103.886 h1.52
  text "OUTER:" at 296.663,103.801 h1.52
  text "1.4MIL (1oz)" at 309.947,99.922 h1.52
  text "2.8MIL (2oz)" at 329.429,99.922 h1.52
  text "N/A" at 347.883,99.931 h1.52
  text "INNER SIGNAL:" at 289.32,99.813 h1.52
  text "X" at 306.72,99.813 h1.52
  text "DRILLING:" at 287.595,96.282 h1.52
  text "REFERENCE:" at 289.494,93.31 h1.52
  text "X" at 305.959,93.31 h1.52
  text "AS SHOWN" at 310.709,93.31 h1.52
  text "X" at 328.845,93.31 h1.52
  text "NC_DRILL FILES" at 332.324,93.31 h1.52
  text "PTH MIN COPPER THICKNESS:" at 289.494,89.297 h1.52
  text "X" at 323.79,89.297 h1.52
  text "1MIL" at 327.27,89.297 h1.52
  text "OTHER" at 339.894,89.297 h1.52
  text "BOARD FINISH:" at 287.595,85.259 h1.52
  text "SILKSCREEN:" at 291.538,82.261 h1.52
  text "X" at 315.637,82.261 h1.52
  text "TOP" at 318.837,82.261 h1.52
  text "X" at 328.591,82.261 h1.52
  text "BOTTOM" at 331.816,82.261 h1.52
  text "SILKSCREEN COLOR:" at 291.538,78.02 h1.52
  text "X" at 315.61,78.02 h1.52
  text "WHITE" at 318.837,78.02 h1.52
  text "OTHER" at 331.816,78.02 h1.52
  text "SOLDER RESIST COLOR:" at 291.538,73.702 h1.52
  text "X" at 305.958,69.658 h1.52
  text "GREEN" at 309.185,69.658 h1.52
  text "BLUE" at 324.196,69.658 h1.52
  text "OTHER" at 337.862,69.658 h1.52
  text "IMMERSION GOLD (ENIG)" at 314.544,64.87 h1.52
  text "ENEPIG" at 348.518,64.786 h1.52
  text "SURFACE FINISH:" at 287.595,64.761 h1.52
  text "X" at 309.796,64.761 h1.52
  text "IMM. TIN/SILVER OR EQUIV" at 295.965,60.773 h1.52
  text "OTHER" at 332.324,60.773 h1.52
  text "ARRAY/PANEL:" at 287.595,56.226 h1.52
  text "CUT AND TRIM PER MECH LAYER 1" at 314.544,56.118 h1.52
  text "N.C. ROUTE" at 314.544,52.264 h1.52
  text "X" at 331.791,52.264 h1.52
  text "V. SCORE" at 336.541,52.264 h1.52
  text "CERTIFICATION:" at 287.595,48.784 h1.52
  text "MATERIALS AND WORKMANSHIP FOR ALL PCBS" at 306.01,48.784 h1.52
  text "TO MEET OR EXCEED THE REQUIREMENTS OF:" at 306.01,46.295 h1.52
  text "X" at 296.523,42.828 h1.52
  text "ANSI IPC-A-600F CLASS ->" at 300.054,42.828 h1.52
  text "X" at 341.686,42.828 h1.52
  text "2" at 344.707,42.828 h1.52
  text "1" at 336.706,42.79 h1.52
  text "3" at 353.699,42.79 h1.52
  text "X" at 296.575,38.777 h1.52
  text "UL 94V-0" at 300.054,38.777 h1.52
  text "X" at 317.2,38.777 h1.52
  text "RoHS" at 320.679,38.777 h1.52
  text "OTHER" at 337.046,38.777 h1.52
  text "PER ORDER" at 347.132,38.777 h1.52
  text "ADDITIONAL REQUIREMENTS:" at 287.595,35.195 h1.52
  text "MICROSECTION:" at 289.494,32.274 h1.52
  text "YES" at 312.5,32.274 h1.52
  text "REQUIRED" at 334.382,28.308 h1.52
  text "BARE BOARD ELEC. TEST:" at 289.494,28.236 h1.52
  text "NONE" at 322.66,28.236 h1.52
  text "X" at 331.156,28.236 h1.52
  text "PER ORDER" at 349.419,28.236 h1.52
  text "MANUFACTURER'S UL:" at 289.494,24.248 h1.52
  text "RAIL" at 319.104,24.139 h1.52
  text "METAL" at 331.596,24.139 h1.52
  text "X" at 341.127,24.13 h1.52
  text "SILK" at 344.593,24.139 h1.52
  text ".Layer_Name" at 14.656,-21.806 h1.52
M11 Gerber Information:
  lines w0.254: -7.417,-23.626 160.223,-23.626 ; -7.417,-18.462 160.274,-18.462 ; -7.417,-13.297 -7.417,-28.791 94.31,-28.791 160.274,-28.791 160.274,-13.297 -7.404,-13.297 -7.404,-28.791 32.614,-28.791 ; 55.194,-28.791 55.194,-13.297 ; 87.376,-18.462 87.376,-13.297 ; 108.712,-18.462 108.712,-13.297 ; 124.511,-28.956 124.511,-23.804
  text "ALL ARTWORK VIEWED FROM TOP SIDE" at -5.804,-16.654 h1.52
  text "BOARD #:" at 57.099,-16.654 h1.52
  text ".PRJ_Number" at 70.955,-16.654 h1.52
  text "REV:" at 92.405,-16.654 h1.52
  text ".PCB_Rev" at 99.809,-16.654 h1.52
  text "SVN REV:" at 113.69,-16.654 h1.52
  text ".VersionControl_RevNumber" at 126.543,-16.654 h1.52
  text "LAYER NAME =" at -5.804,-21.806 h1.52
  text "PLOT NAME =" at -5.804,-27.034 h1.52
  text ".plot_File_Name" at 14.656,-27.034 h1.52
  text "GENERATED    :" at 57.15,-27.034 h1.52
  text ".Print_Date" at 79.235,-27.034 h1.52
  text ".Print_Time" at 97.752,-27.034 h1.52
  text "TEXAS INSTRUMENTS" at 129.87,-27.034 h1.52
M12 Stackup:
  lines w0.152: 288.544,189.484 353.314,189.484 ; 288.544,192.136 353.314,192.136 ; 287.02,177.165 ccw(c287.884,177.165) 287.884,176.301 353.974,176.301 ccw(c353.974,177.165) 354.838,177.165 354.838,195.097 ccw(c353.974,195.097) 353.974,195.961 287.884,195.961 ccw(c287.884,195.097) 287.02,195.097 287.02,177.165
  text "The Stackup Legend below this is static." at 294.78,200.012 h1.52
  text "If you change the stackup, update the Legend." at 295.034,197.726 h1.52
  text "Layer Stack Up Detail for: Ref_Design.PcbDoc" at 288.544,192.966 h1.45
  text "Layer" at 288.544,191.145 h0.61
  text "Gerber" at 311.298,191.145 h0.61
  text "Copper" at 325.611,191.145 h0.61
  text "Dielectric" at 340.92,191.145 h0.61
  text "Name" at 288.544,189.926 h0.61
  text "Document" at 311.298,189.926 h0.61
  text "Thickness" at 325.611,189.926 h0.61
  text "Material" at 340.92,189.926 h0.61
  text "Top Solder Mask" at 288.544,187.565 h0.86
  text "(.GTS)" at 311.298,187.565 h0.86
  text "Solder Resist" at 340.92,187.565 h0.86
  text "Top Layer" at 288.544,185.107 h0.86
  text "(.GTL)" at 311.298,185.107 h0.86
  text "1.4mil" at 325.611,185.107 h0.86
  text "FR-4" at 340.92,183.879 h0.86
  text "Bottom Layer" at 288.544,182.65 h0.86
  text "(.GBL)" at 311.298,182.65 h0.86
  text "1.4mil" at 325.611,182.65 h0.86
  text "Bottom Solder Mask" at 288.544,180.192 h0.86
  text "(.GBS)" at 311.298,180.192 h0.86
  text "Solder Resist" at 340.92,180.192 h0.86
  text ".Layer_Name" at 14.656,-21.806 h1.52
M13 Component Bodies Top:
  text ".Layer_Name" at 14.656,-21.806 h1.52
M14 Component Bodies Bottom:
  text ".Layer_Name" at 14.656,-21.806 h1.52
M15 Courtyards Top:
  text ".Layer_Name" at 14.656,-21.806 h1.52
M16 Courtyards Bottom:
  text ".Layer_Name" at 14.656,-21.806 h1.52
Drill Drawing:
  text ".Layer_Name" at 14.656,-21.806 h1.52

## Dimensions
0,0 to 261.62,0 on M2 Board Dimensions
0,-0.127 to 0,149.86 on M2 Board Dimensions
67.183,133.096 to 116.183,92.964 on M1 Board Outline
116.183,92.964 to 116.183,133.096 on M1 Board Outline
